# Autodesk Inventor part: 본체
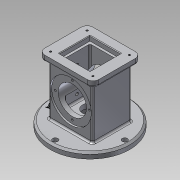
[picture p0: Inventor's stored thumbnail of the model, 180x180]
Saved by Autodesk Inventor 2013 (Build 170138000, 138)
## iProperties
Created: 2005-01
Part Number: 본체
Material: 알루미늄 6061
Document SubType Name: Modeling
Designer: hana-cad36
Density: 2.40731 g/cm^3
Mass: 926.229 g
Surface Area: 783.577 cm^2
Volume: 384.757 cm^3
Author: hana-cad36
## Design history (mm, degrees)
sketch "스케치1"
  geometry: C1 r 67.5 at (0, 0); 1 further point
  constraints: 1 centre point, 1 coincident
  dimensions: "d0" = 135 diameter of C1
extrude "돌출1" new body sketch "스케치1" distance "d2" = 10; taper "d3" = 0 deg
chamfer "모따기1" distance "d4" = 3; stored, may be unused: second distance "d5" = 2, angle "d6" = 45 deg
sketch "스케치2"
  geometry: C1 r 64.5 at (0, 0) reference; A1 r 59 centre (0, 0) between (0, 59) and (59, 0); 1 further point
  constraints: 3 point on circle, 2 vertical alignment, 1 centre point, 1 coincident, 1 horizontal alignment
  dimensions: "d7" = 118 diameter of A1
hole "구멍1" sketch "스케치2" at (0, 59), (59, 0), (0, -59) diameter "d9" = 9; stored, may be unused: countersink angle "d13" = 90 deg, drill point angle "d15" = 118 deg; dims "d10" = 6, "d11" = 4, "d12" = 2, "d14" = 8
sketch "스케치3"
  geometry: L1 (-37, -33)-(37, -33); L2 (37, -33)-(37, 33); L3 (37, 33)-(-37, 33); L4 (-37, 33)-(-37, -33); L5 (-37, -33)-(37, 33); L6 (37, -33)-(-37, 33); C1 r 64.5 at (0, 0) reference
  constraints: 12 end point, 2 midpoint, 2 parallel, 1 horizontal, 1 perpendicular
  dimensions: "d16" = 74 distance of L2.end L3.end; "d17" = 66 distance of L1.end L2.end
extrude "돌출2" join sketch "스케치3" distance "d18" = 88; taper "d19" = 0 deg
sketch "스케치4"
  geometry: L1 (-46, -41)-(46, -41); L2 (46, -41)-(46, 41); L3 (46, 41)-(-46, 41); L4 (-46, 41)-(-46, -41); L5 (-46, -41)-(46, 41); L6 (46, -41)-(-46, 41); 1 further point
  constraints: 12 end point, 2 midpoint, 2 parallel, 1 horizontal, 1 perpendicular
  dimensions: "d20" = 92 distance of L2.end L3.end; "d21" = 82 distance of L1.end L2.end
extrude "돌출3" join sketch "스케치4" distance "d22" = 10; taper "d23" = 0 deg
sketch "스케치5"
  geometry: L1 (-30.5, -10)-(104.5, -10) reference; C1 r 35 at (37, 44); 2 further points
  constraints: 1 centre point, 1 midpoint, 1 vertical alignment
  dimensions: "d24" = 70 diameter of C1; "d28" = 54 distance from line of L1 C1.centre
extrude "돌출4" cut sketch "스케치5" distance "d26" = 3; taper "d27" = 0 deg
sketch "스케치6"
  geometry: C1 r 35 at (0, 0) reference; C2 r 24 at (0, 0); 1 further point
  constraints: 1 centre point, 1 coincident
  dimensions: "d29" = 48 diameter of C2
extrude "돌출5" cut sketch "스케치6" stored distance "d31" = 3; taper "d32" = 0 deg
sketch "스케치7"
  geometry: L1 (-26, -26)-(26, -26); L2 (26, -26)-(26, 26); L3 (26, 26)-(-26, 26); L4 (-26, 26)-(-26, -26); L5 (-26, -26)-(26, 26); L6 (26, -26)-(-26, 26); 1 further point
  constraints: 12 end point, 2 midpoint, 2 parallel, 1 horizontal, 1 perpendicular
  dimensions: "d33" = 52 distance of L2.end L3.end; "d34" = 52 distance of L1.end L2.end
extrude "돌출6" cut sketch "스케치7" distance "d35" = 8; taper "d36" = 0 deg
sketch "스케치8"
  geometry: L1 (-22, -22)-(22, -22); L2 (22, -22)-(22, 22); L3 (22, 22)-(-22, 22); L4 (-22, 22)-(-22, -22); L5 (-22, -22)-(22, 22); L6 (22, -22)-(-22, 22); 1 further point
  constraints: 12 end point, 2 midpoint, 2 parallel, 1 horizontal, 1 perpendicular
  dimensions: "d37" = 44 distance of L2.end L3.end; "d38" = 44 distance of L1.end L2.end
extrude "돌출7" cut sketch "스케치8" distance "d39" = 74; taper "d40" = 0 deg
sketch "스케치9"
  geometry: C1 r 67.5 at (0, 0) reference; C2 r 25 at (0, 0)
  constraints: 1 centre point, 1 coincident
  dimensions: "d41" = 50 diameter of C2
extrude "돌출8" cut sketch "스케치9" distance "d43" = 18; taper "d44" = 0 deg
sketch "스케치10"
  geometry: C1 r 25 at (0, 0) reference; C2 r 12.5 at (0, 0)
  constraints: 1 centre point, 1 coincident
  dimensions: "d45" = 25 diameter of C2
extrude "돌출9" cut sketch "스케치10" stored distance "d47" = 18; taper "d48" = 0 deg
fillet "모깎기1" dims "d49" = 10
chamfer "모따기2" distance "d50" = 1; stored, may be unused: second distance "d51" = 2, angle "d52" = 45 deg
fillet "모깎기2" dims "d53" = 3
fillet "모깎기3" dims "d54" = 3
fillet "모깎기4" dims "d55" = 3
node "작업 평면1"
sketch "스케치11"
  geometry: C1 r 59 at (0, 0); 1 further point
  constraints: 1 centre point, 1 coincident, 1 other
  dimensions: "d57" = 118 diameter of C1
feature "엠보싱1" sketch "스케치11" dims "d16" = 74, "d59" = 0.5, "d60" = 0
sketch "스케치12" dims "d61" = 58
  geometry: C1 r 24 at (0, 0) reference; C2 r 35 at (0, 0) reference; 3 further points
  constraints: 2 vertical alignment, 1 coincident, 2 other
hole "구멍2" sketch "스케치12" at (0, 29) diameter "d63" = 3.242; stored, may be unused: countersink angle "d67" = 90 deg, drill point angle "d69" = 118 deg; dims "d64" = 4, "d65" = 4, "d66" = 2, "d68" = 6
sketch "스케치13"
  geometry: A1 r 10 centre (-36, 31) between (-36, 41) and (-46, 31) reference; A2 r 10 centre (-36, -31) between (-46, -31) and (-36, -41) reference; A3 r 10 centre (36, -31) between (36, -41) and (46, -31) reference; A4 r 10 centre (36, 31) between (46, 31) and (36, 41) reference; 1 further point
hole "구멍3" sketch "스케치13" at (36, -31), (36, 31), (-36, 31), (-36, -31) diameter "d73" = 3.242; stored, may be unused: countersink angle "d77" = 90 deg, drill point angle "d79" = 118 deg; dims "d74" = 4, "d75" = 4, "d76" = 2, "d78" = 6
sketch "스케치14"
  geometry: L1 (-10, 100.5)-(-10, -34.5) reference; 4 further points
  constraints: 2 horizontal alignment, 1 midpoint
  dimensions: "d80" = 37 distance from line of L1 point (27, 33); "d81" = 43 distance of point (27, 33) point (70, 33)
hole "구멍4" sketch "스케치14" at (70, 33), (27, 33) diameter "d82" = 4.917; stored, may be unused: countersink angle "d86" = 90 deg, drill point angle "d88" = 118 deg; dims "d83" = 15, "d84" = 4, "d85" = 2, "d87" = 15
fillet "모깎기5" dims "d89" = 3
fillet "모깎기6" dims "d90" = 3
fillet "모깎기7" dims "d91" = 3
node "솔리드1"
mirror "대칭1"
pattern_circular "원형 패턴1" dims angle "d71" = 360 deg
mirror "대칭2"
other parameters: "d56" = 8.75
